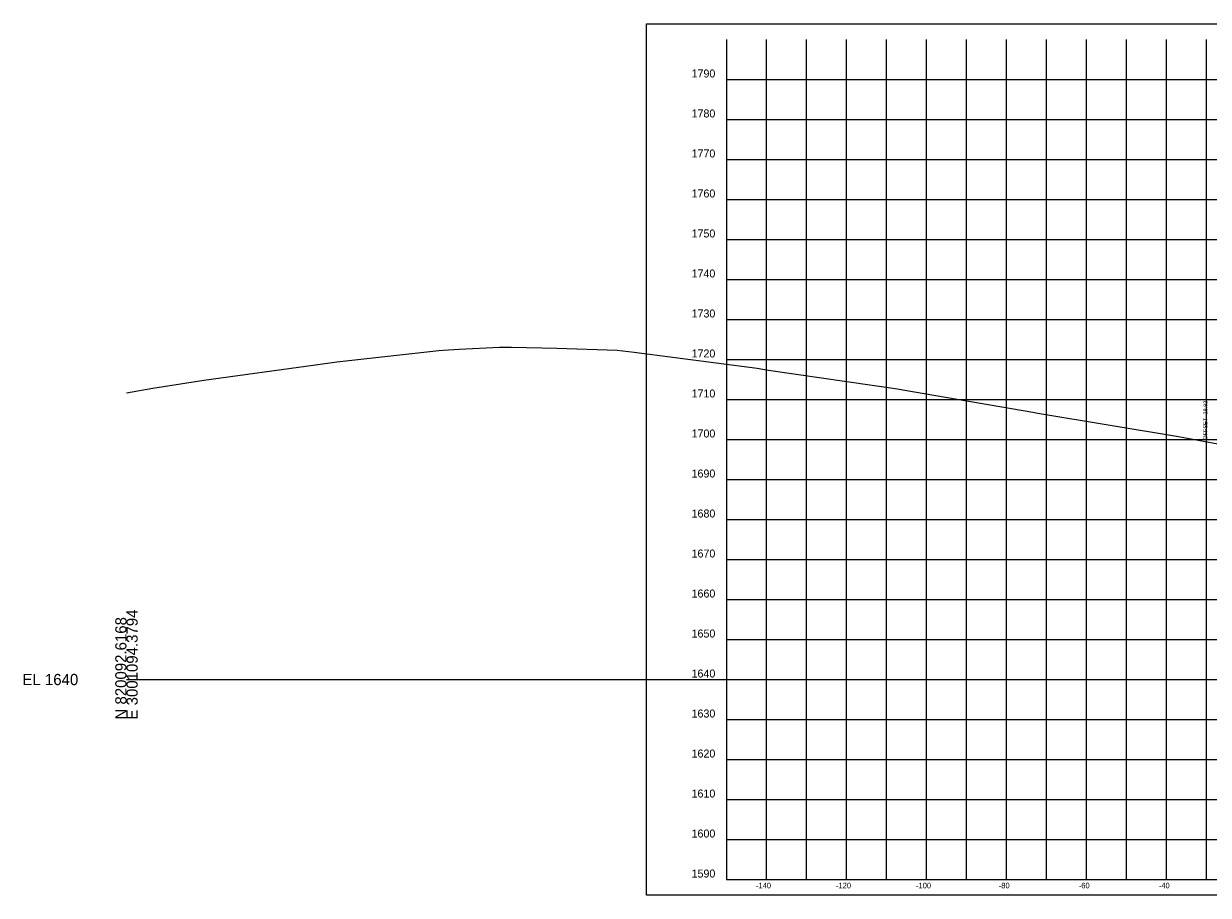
# Model space of a CAD drawing. Extents: x -26 to 603, y -61 to 1770.
# Drawn here: x -25.7 to 270.4, y 446.1 to 663.9 of the extents above; entities that cross this region are included whole.
import ezdxf

# ---------------------------------------------------------------- set-up
doc = ezdxf.new("R2010")
doc.units = 0
for name, color, linetype in [('DESIGN - SHEET - Corner Text', 7, 'Continuous'), ('DESIGN - SHEET - Light Grid', 7, 'Continuous'), ('DESIGN - SHEET - Linework', 7, 'Continuous'), ('DESIGN - SHEET - Plot Shape', 7, 'Continuous'), ('DESIGN - TYPICAL - Slope Tie Text', 7, 'Continuous'), ('SURVEY - GROUND - Top of Ground', 7, 'Continuous')]:
    doc.layers.add(name, color=color, linetype=linetype)

msp = doc.modelspace()

# ---------------------------------------------------------------- linework, layer by layer
at = {"layer": 'DESIGN - SHEET - Light Grid'}
msp.add_line((0, 500), (300, 500), dxfattribs=at)
at = {"layer": 'DESIGN - SHEET - Linework'}
for p, q in [((160, 450), (160, 660)), ((170, 450), (170, 660)), ((180, 450), (180, 660)), ((190, 450), (190, 660)), ((200, 450), (200, 660)), ((210, 450), (210, 660)), ((220, 450), (220, 660)), ((230, 450), (230, 660)), ((240, 450), (240, 660)), ((250, 450), (250, 660)), ((260, 450), (260, 660)), ((270, 450), (270, 660)), ((150, 650), (450, 650)), ((150, 640), (450, 640)), ((150, 630), (450, 630)), ((150, 620), (450, 620)), ((150, 610), (450, 610)), ((150, 600), (450, 600)), ((150, 590), (450, 590)), ((150, 580), (450, 580)), ((150, 570), (450, 570)), ((150, 560), (450, 560)), ((150, 550), (450, 550)), ((150, 540), (450, 540)), ((150, 530), (450, 530)), ((150, 520), (450, 520)), ((150, 510), (450, 510)), ((150, 500), (450, 500)), ((150, 490), (450, 490)), ((150, 480), (450, 480)), ((150, 470), (450, 470)), ((150, 460), (450, 460))]:
    msp.add_line(p, q, dxfattribs=at)
msp.add_lwpolyline([(150, 660), (150, 450), (450, 450), (450, 660)], dxfattribs=at)
at = {"layer": 'DESIGN - SHEET - Plot Shape'}
msp.add_lwpolyline([(130, 663.94), (470, 663.94), (470, 446.06), (130, 446.06)], close=True, dxfattribs=at)
at = {"layer": 'SURVEY - GROUND - Top of Ground'}
msp.add_lwpolyline([(0, 571.65), (6.57, 572.79), (17.74, 574.57), (19.37, 574.84), (47.29, 578.7), (52.6, 579.41), (78.11, 582.24), (79.16, 582.36), (83.12, 582.55), (93.24, 583.09), (96.24, 583.12), (107.61, 582.8), (122.66, 582.35), (126.89, 581.81), (157.69, 577.79), (160.5, 577.35), (192.72, 572.66), (194.1, 572.41), (226.59, 566.82), (227.81, 566.61), (262.99, 560.71), (295.15, 554.78)], dxfattribs=at)

# ---------------------------------------------------------------- texts
at = {"layer": 'DESIGN - SHEET - Corner Text'}
for s, height, p in [('1790', 2, (141.25, 650.5)), ('1780', 2, (141.25, 640.5)), ('1770', 2, (141.25, 630.5)), ('1760', 2, (141.25, 620.5)), ('1750', 2, (141.25, 610.5)), ('1740', 2, (141.25, 600.5)), ('1730', 2, (141.25, 590.5)), ('1720', 2, (141.25, 580.5)), ('1710', 2, (141.25, 570.5)), ('1700', 2, (141.25, 560.5)), ('1690', 2, (141.25, 550.5)), ('1680', 2, (141.25, 540.5)), ('1670', 2, (141.25, 530.5)), ('1660', 2, (141.25, 520.5)), ('1650', 2, (141.25, 510.5)), ('1640', 2, (141.25, 500.5)), ('1630', 2, (141.25, 490.5)), ('1620', 2, (141.25, 480.5)), ('1610', 2, (141.25, 470.5)), ('1600', 2, (141.25, 460.5)), ('1590', 2, (141.25, 450.5)), ('-140', 1.4, (157.37, 447.8)), ('-120', 1.4, (177.37, 447.8)), ('-100', 1.4, (197.37, 447.8)), ('-80', 1.4, (218.06, 447.8)), ('-60', 1.4, (238.06, 447.8)), ('-40', 1.4, (258.06, 447.8))]:
    msp.add_text(s, height=height, dxfattribs=at).set_placement(p)
at = {"layer": 'DESIGN - SHEET - Light Grid'}
for s, p in [('N 820092.6168', (0, 490)), ('E 3001094.3794', (2.8, 490))]:
    msp.add_text(s, height=2.8, rotation=90, dxfattribs=at).set_placement(p)
msp.add_text('EL 1640', height=2.8, dxfattribs=at).set_placement((-26, 498.6))
at = {"layer": 'DESIGN - TYPICAL - Slope Tie Text'}
msp.add_text('OFFSET -28.82', height=1, rotation=90, dxfattribs=at).set_placement((270.18, 559.95))

doc.saveas('drawing.dxf')
